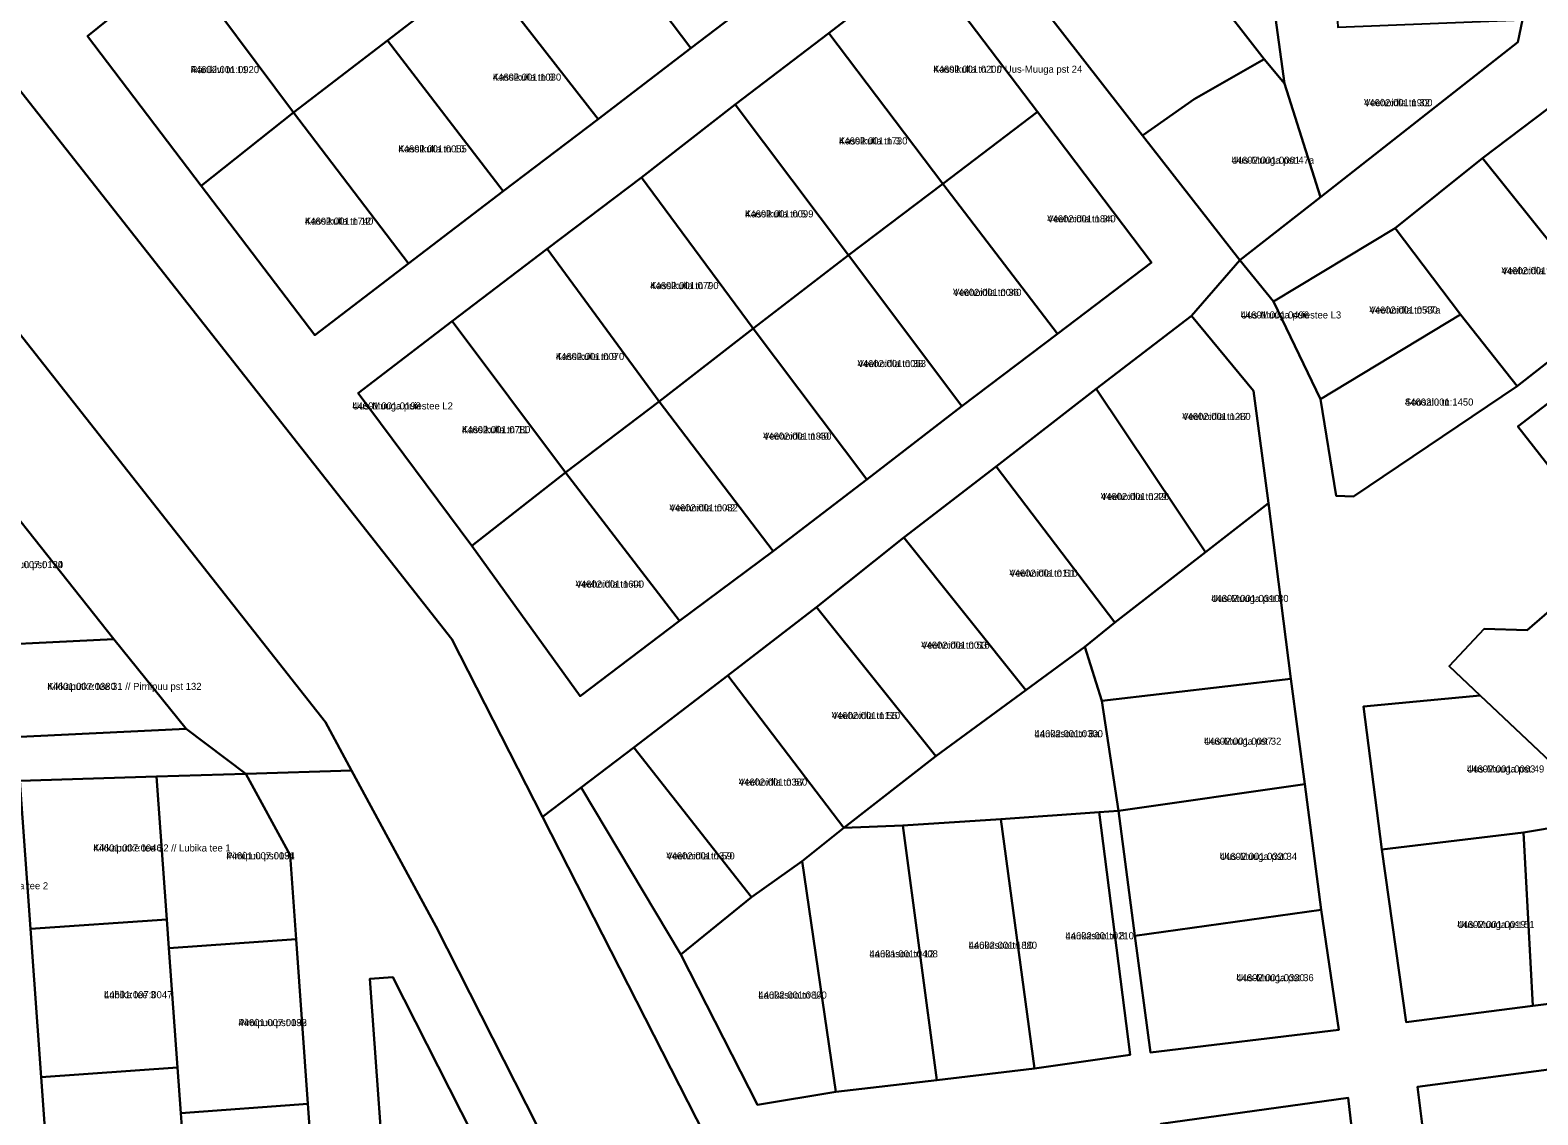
# Model space of a CAD drawing. Extents: x 551843 to 558501, y 6589003 to 6595718.
# Drawn here: x 554378.5 to 554698.1, y 6593216.1 to 6593446 of the extents above; entities that cross this region are included whole.
import ezdxf

# ---------------------------------------------------------------- set-up
doc = ezdxf.new("R2010")
doc.units = 0
for name, color, linetype in [('L_AADRESS', 7, 'Continuous'), ('PIIR', 7, 'Continuous'), ('TUNNUS', 7, 'Continuous')]:
    doc.layers.add(name, color=color, linetype=linetype)

msp = doc.modelspace()

# ---------------------------------------------------------------- linework, layer by layer
at = {"layer": 'PIIR'}
for points in [[(554558.39, 6593472.91), (554533.97, 6593504.96), (554509.47, 6593537.37), (554489.67, 6593522), (554469.89, 6593506.62), (554449.82, 6593491.18), (554430.33, 6593476.01), (554424.48, 6593471.49), (554410.37, 6593460.67), (554390.71, 6593444.69), (554414.79, 6593413.03), (554438.86, 6593381.38), (554458.73, 6593396.56), (554478.79, 6593411.86), (554498.88, 6593427.13), (554518.54, 6593442.19), (554538.24, 6593457.19)], [(554494.38, 6593474.18), (554514.29, 6593489.75), (554538.24, 6593457.19), (554518.54, 6593442.19)], [(554644.4, 6593434.65), (554640.09, 6593439.84), (554616.78, 6593469.9), (554611.24, 6593477.76), (554637.08, 6593488.85), (554641.71, 6593454.64), (554642.5, 6593448.58)], [(554494.38, 6593474.18), (554518.54, 6593442.19), (554498.88, 6593427.13), (554474.07, 6593459.05)], [(554434.36, 6593428.54), (554410.37, 6593460.67), (554424.48, 6593471.49), (554428.06, 6593466.74), (554433.16, 6593460), (554440.31, 6593450.67), (554445.4, 6593449.86), (554457.04, 6593458.74), (554463.12, 6593450.6), (554454.26, 6593443.78)], [(554640.09, 6593439.84), (554625.24, 6593431.4), (554614.3, 6593423.64), (554593.05, 6593450.89), (554596.18, 6593453.39), (554616.78, 6593469.9)], [(554434.36, 6593428.54), (554414.79, 6593413.03), (554390.71, 6593444.69), (554410.37, 6593460.67)], [(554592.06, 6593428.7), (554567.74, 6593460.75), (554547.83, 6593445.37), (554527.95, 6593430.21), (554508.09, 6593414.78), (554488.08, 6593399.67), (554467.99, 6593384.32), (554448.06, 6593369.09), (554472.14, 6593336.71), (554495.13, 6593304.83), (554516.12, 6593320.8), (554536.02, 6593335.58), (554555.87, 6593350.77), (554576, 6593366.27), (554596.28, 6593381.66), (554616.22, 6593396.76)], [(554571.97, 6593413.39), (554547.83, 6593445.37), (554567.74, 6593460.75), (554592.06, 6593428.7)], [(554474.07, 6593459.05), (554498.88, 6593427.13), (554478.79, 6593411.86), (554454.26, 6593443.78), (554463.12, 6593450.6)], [(554642.5, 6593448.58), (554655.54, 6593449.15), (554655.7, 6593446.61), (554694.84, 6593448.21), (554693.84, 6593443.43), (554652, 6593410.62), (554644.4, 6593434.65)], [(554547.83, 6593445.37), (554571.97, 6593413.39), (554551.98, 6593398.31), (554527.95, 6593430.21)], [(554454.26, 6593443.78), (554478.79, 6593411.86), (554458.73, 6593396.56), (554434.36, 6593428.54)], [(554614.3, 6593423.64), (554625.24, 6593431.4), (554640.09, 6593439.84), (554644.4, 6593434.65), (554652, 6593410.62), (554634.9, 6593397.21)], [(554705.79, 6593433.58), (554731.82, 6593401.1), (554723.48, 6593394.34), (554712.94, 6593385.68), (554686.35, 6593418.84)], [(554434.36, 6593428.54), (554458.73, 6593396.56), (554438.86, 6593381.38), (554414.79, 6593413.03)], [(554508.09, 6593414.78), (554527.95, 6593430.21), (554551.98, 6593398.31), (554531.79, 6593382.79)], [(554592.06, 6593428.7), (554616.22, 6593396.76), (554596.28, 6593381.66), (554571.97, 6593413.39)], [(554667.8, 6593404.05), (554686.35, 6593418.84), (554712.94, 6593385.68), (554693.67, 6593370.54), (554681.65, 6593385.7)], [(554531.79, 6593382.79), (554511.87, 6593367.29), (554488.08, 6593399.67), (554508.09, 6593414.78)], [(554571.97, 6593413.39), (554596.28, 6593381.66), (554576, 6593366.27), (554551.98, 6593398.31)], [(554667.8, 6593404.05), (554681.65, 6593385.7), (554651.99, 6593367.81), (554642.02, 6593388.52)], [(554488.08, 6593399.67), (554511.87, 6593367.29), (554491.99, 6593352.28), (554467.99, 6593384.32)], [(554551.98, 6593398.31), (554576, 6593366.27), (554555.87, 6593350.77), (554531.79, 6593382.79)], [(554467.99, 6593384.32), (554491.99, 6593352.28), (554472.14, 6593336.71), (554448.06, 6593369.09)], [(554624.63, 6593385.48), (554637.8, 6593369.53), (554640.97, 6593345.75), (554627.66, 6593335.39), (554604.43, 6593369.96)], [(554681.65, 6593385.7), (554693.67, 6593370.54), (554659.03, 6593347.16), (554655.35, 6593347.33), (554651.99, 6593367.81)], [(554531.79, 6593382.79), (554555.87, 6593350.77), (554536.02, 6593335.58), (554511.87, 6593367.29)], [(554713.27, 6593376.87), (554728.26, 6593376.39), (554730.89, 6593348.69), (554715.53, 6593334.32), (554693.81, 6593362.03)], [(554604.43, 6593369.96), (554627.66, 6593335.39), (554608.44, 6593320.44), (554583.24, 6593353.55)], [(554491.99, 6593352.28), (554511.87, 6593367.29), (554536.02, 6593335.58), (554516.12, 6593320.8)], [(554491.99, 6593352.28), (554516.12, 6593320.8), (554495.13, 6593304.83), (554472.14, 6593336.71)], [(554583.24, 6593353.55), (554608.44, 6593320.44), (554602.09, 6593315.33), (554589.57, 6593306.11), (554563.69, 6593338.49)], [(554358.84, 6593315.1), (554357.18, 6593340.35), (554357.01, 6593347.99), (554370.87, 6593348.86), (554396.28, 6593316.9)], [(554602.09, 6593315.33), (554608.44, 6593320.44), (554627.66, 6593335.39), (554640.97, 6593345.75), (554645.69, 6593308.53), (554605.66, 6593303.87)], [(554563.69, 6593338.49), (554589.57, 6593306.11), (554570.45, 6593292.11), (554545.19, 6593323.7)], [(554686.66, 6593319.08), (554695.78, 6593318.83), (554708.92, 6593330.24), (554724.18, 6593306.39), (554703.25, 6593288.59), (554685.85, 6593304.98), (554679.24, 6593311.2)], [(554545.19, 6593323.7), (554570.45, 6593292.11), (554550.95, 6593276.97), (554526.37, 6593309.22)], [(554358.84, 6593315.1), (554396.28, 6593316.9), (554411.57, 6593297.9), (554360.13, 6593295.44)], [(554563.47, 6593277.43), (554550.95, 6593276.97), (554570.45, 6593292.11), (554589.57, 6593306.11), (554602.09, 6593315.33), (554605.66, 6593303.87), (554609.16, 6593280.58), (554605.1, 6593280.26), (554584.23, 6593278.78)], [(554526.37, 6593309.22), (554550.95, 6593276.97), (554542.17, 6593269.88), (554531.39, 6593262.22), (554506.48, 6593294)], [(554605.66, 6593303.87), (554645.69, 6593308.53), (554648.68, 6593286.23), (554609.16, 6593280.58)], [(554661.09, 6593302.65), (554685.85, 6593304.98), (554703.25, 6593288.59), (554712.28, 6593278.85), (554695.05, 6593275.98), (554664.98, 6593272.36)], [(554506.48, 6593294), (554531.39, 6593262.22), (554516.42, 6593250.12), (554495.31, 6593285.5)], [(554405.33, 6593287.82), (554424.25, 6593288.4), (554433.6, 6593271.12), (554434.88, 6593253.34), (554407.95, 6593251.41), (554407.5, 6593257.53)], [(554405.33, 6593287.82), (554407.5, 6593257.53), (554378.58, 6593255.52), (554376.33, 6593286.93)], [(554609.16, 6593280.58), (554648.68, 6593286.23), (554652.14, 6593259.57), (554612.67, 6593254.06)], [(554563.47, 6593277.43), (554584.23, 6593278.78), (554591.4, 6593225.96), (554570.66, 6593223.48)], [(554584.23, 6593278.78), (554605.1, 6593280.26), (554611.67, 6593228.8), (554591.4, 6593225.96)], [(554712.28, 6593278.85), (554717.2, 6593271.06), (554734.16, 6593243.86), (554697, 6593239.23), (554695.05, 6593275.98)], [(554550.95, 6593276.97), (554563.47, 6593277.43), (554570.66, 6593223.48), (554549.31, 6593220.98), (554542.17, 6593269.88)], [(554695.05, 6593275.98), (554697, 6593239.23), (554670.13, 6593235.73), (554664.98, 6593272.36)], [(554531.39, 6593262.22), (554542.17, 6593269.88), (554549.31, 6593220.98), (554532.71, 6593218.23), (554516.42, 6593250.12)], [(554652.14, 6593259.57), (554655.91, 6593234.16), (554615.95, 6593229.3), (554612.67, 6593254.06)], [(554407.5, 6593257.53), (554407.95, 6593251.41), (554409.76, 6593226.17), (554380.84, 6593224.1), (554378.58, 6593255.52)], [(554434.88, 6593253.34), (554437.39, 6593218.43), (554410.46, 6593216.5), (554409.76, 6593226.17), (554407.95, 6593251.41)], [(554450.52, 6593244.94), (554455.4, 6593245.29), (554481.92, 6593193.06), (554454.39, 6593191.08)], [(554455.4, 6593245.29), (554450.52, 6593244.94), (554454.39, 6593191.08), (554456.32, 6593164.15), (554458.04, 6593140.21), (554460.41, 6593107.3), (554462.99, 6593071.39), (554496.9, 6593073.82), (554494.96, 6593100.76), (554506.93, 6593101.61), (554508.87, 6593074.68), (554540.84, 6593076.98), (554533.65, 6593091.16), (554527.59, 6593103.1), (554506.96, 6593143.72), (554495.17, 6593166.94), (554481.92, 6593193.06)], [(554711.65, 6593227.21), (554715.19, 6593202.16), (554675.67, 6593197.16), (554672.53, 6593222.08)], [(554409.76, 6593226.17), (554410.46, 6593216.5), (554412.02, 6593194.75), (554383.09, 6593192.68), (554380.84, 6593224.1)], [(554412.96, 6593181.59), (554412.02, 6593194.75), (554410.46, 6593216.5), (554437.39, 6593218.43), (554439.89, 6593183.52)], [(554657.88, 6593219.71), (554660.66, 6593195.18), (554621.17, 6593189.78), (554618.16, 6593214.22)]]:
    msp.add_lwpolyline(points, close=True, dxfattribs=at)
for points in [[(554923.69, 6592347.53), (554878.41, 6592438.09), (554841.8, 6592510.41), (554771.18, 6592649.95), (554642.95, 6592903.73), (554573.43, 6593041.09), (554529.22, 6593128.57), (554464.48, 6593256.08), (554446.62, 6593289.09), (554441.09, 6593299.31), (554261.19, 6593527.78)], [(554261.19, 6593527.78), (554441.09, 6593299.31), (554446.62, 6593289.09), (554424.25, 6593288.4), (554411.57, 6593297.9), (554396.28, 6593316.9), (554370.87, 6593348.86)], [(554309.59, 6593518.04), (554467.93, 6593316.95), (554487.14, 6593279.28), (554574.16, 6593108.63)], [(554593.05, 6593450.89), (554614.3, 6593423.64), (554634.9, 6593397.21), (554624.63, 6593385.48), (554604.43, 6593369.96), (554583.24, 6593353.55), (554563.69, 6593338.49), (554545.19, 6593323.7), (554526.37, 6593309.22), (554506.48, 6593294), (554495.31, 6593285.5), (554487.14, 6593279.28), (554467.93, 6593316.95), (554309.59, 6593518.04)], [(554705.79, 6593433.58), (554686.35, 6593418.84), (554667.8, 6593404.05), (554642.02, 6593388.52), (554634.9, 6593397.21), (554652, 6593410.62), (554693.84, 6593443.43), (554694.84, 6593448.21)], [(554574.16, 6593108.63), (554487.14, 6593279.28), (554495.31, 6593285.5), (554516.42, 6593250.12), (554532.71, 6593218.23), (554549.31, 6593220.98), (554570.66, 6593223.48), (554591.4, 6593225.96), (554611.67, 6593228.8), (554605.1, 6593280.26), (554609.16, 6593280.58), (554612.67, 6593254.06), (554615.95, 6593229.3), (554655.91, 6593234.16), (554652.14, 6593259.57), (554648.68, 6593286.23), (554645.69, 6593308.53), (554640.97, 6593345.75), (554637.8, 6593369.53), (554624.63, 6593385.48), (554634.9, 6593397.21), (554642.02, 6593388.52), (554651.99, 6593367.81), (554655.35, 6593347.33), (554659.03, 6593347.16), (554693.67, 6593370.54), (554712.94, 6593385.68)], [(554713.27, 6593376.87), (554693.81, 6593362.03), (554715.53, 6593334.32)], [(554708.92, 6593330.24), (554695.78, 6593318.83), (554686.66, 6593319.08), (554679.24, 6593311.2), (554685.85, 6593304.98), (554661.09, 6593302.65), (554664.98, 6593272.36), (554670.13, 6593235.73), (554697, 6593239.23), (554734.16, 6593243.86)], [(554360.13, 6593295.44), (554411.57, 6593297.9), (554424.25, 6593288.4), (554405.33, 6593287.82), (554376.33, 6593286.93)], [(554439.89, 6593183.52), (554437.39, 6593218.43), (554434.88, 6593253.34), (554433.6, 6593271.12), (554424.25, 6593288.4), (554446.62, 6593289.09), (554464.48, 6593256.08), (554529.22, 6593128.57)], [(554376.33, 6593286.93), (554378.58, 6593255.52), (554380.84, 6593224.1), (554383.09, 6593192.68), (554385.35, 6593161.26), (554387.61, 6593129.84), (554389.86, 6593098.42), (554392.17, 6593066.3), (554393.23, 6593051.33), (554367.77, 6593049.72)], [(554715.19, 6593202.16), (554711.65, 6593227.21), (554672.53, 6593222.08), (554675.67, 6593197.16)], [(554660.66, 6593195.18), (554657.88, 6593219.71), (554618.16, 6593214.22)]]:
    msp.add_lwpolyline(points, dxfattribs=at)

# ---------------------------------------------------------------- texts
at = {"layer": 'L_AADRESS'}
for s, p in [('Ränikivi tn 11', (554412.54, 6593436.88)), ('Kassikulla tn 1 // Uus-Muuga pst 24', (554569.95, 6593436.96)), ('Kassikulla tn 8', (554476.57, 6593435.29)), ('Veehoidla tn 32', (554661.24, 6593429.88)), ('Kassikulla tn 3', (554549.96, 6593421.77)), ('Kassikulla tn 10', (554456.57, 6593420.08)), ('Uus-Muuga pst 47a', (554633.15, 6593417.68)), ('Kassikulla tn 12', (554436.76, 6593404.77)), ('Kassikulla tn 5', (554530.04, 6593406.3)), ('Veehoidla tn 34', (554594.09, 6593405.26)), ('Veehoidla tn 45', (554690.37, 6593394.26)), ('Kassikulla tn 7', (554509.93, 6593391.11)), ('Veehoidla tn 36', (554574.13, 6593389.67)), ('Veehoidla tn 47a', (554662.37, 6593385.93)), ('Uus-Muuga puiestee L3', (554635.09, 6593384.89)), ('Kassikulla tn 9', (554489.93, 6593376.09)), ('Veehoidla tn 38', (554553.89, 6593374.58)), ('Soosalu tn 1', (554669.9, 6593366.43)), ('Uus-Muuga puiestee L2', (554446.82, 6593365.61)), ('Veehoidla tn 47', (554622.7, 6593363.38)), ('Kassikulla tn 11', (554470.03, 6593360.58)), ('Veehoidla tn 40', (554533.87, 6593359.21)), ('Veehoidla tn 42', (554514.01, 6593344.02)), ('Veehoidla tn 49', (554605.45, 6593346.41)), ('Pirnipuu pst 130', (554371.01, 6593331.98)), ('Veehoidla tn 44', (554494.13, 6593327.85)), ('Veehoidla tn 51', (554586.06, 6593330.17)), ('Uus-Muuga pst 30', (554628.84, 6593324.81)), ('Veehoidla tn 53', (554567.38, 6593314.91)), ('Kikkaputke tee 31 // Pirnipuu pst 132', (554382.17, 6593306.17)), ('Veehoidla tn 55', (554548.41, 6593299.99)), ('Laukasoo tn 8a', (554591.39, 6593296.15)), ('Uus-Muuga pst 32', (554627.31, 6593294.55)), ('Uus-Muuga pst 49', (554683.03, 6593288.67)), ('Veehoidla tn 57', (554528.71, 6593285.89)), ('Kikkaputke tee 32 // Lubika tee 1', (554391.91, 6593271.93)), ('Pirnipuu pst 134', (554420.11, 6593270.28)), ('Veehoidla tn 59', (554513.35, 6593270.25)), ('Uus-Muuga pst 34', (554630.65, 6593270.15)), ('Kikkaputke tee 30 // Lubika tee 2', (554353.23, 6593263.91)), ('Uus-Muuga pst 51', (554680.99, 6593255.72)), ('Laukasoo tn 10', (554577.43, 6593251.31)), ('Laukasoo tn 8', (554597.95, 6593253.32)), ('Laukasoo tn 12', (554556.41, 6593249.49)), ('Uus-Muuga pst 36', (554634.17, 6593244.44)), ('Lubika tee 3', (554394.17, 6593240.83)), ('Laukasoo tn 14', (554532.87, 6593240.76)), ('Pirnipuu pst 136', (554422.67, 6593234.92))]:
    msp.add_text(s, height=1.5, dxfattribs=at).set_placement(p)
at = {"layer": 'TUNNUS'}
for s, p in [('44602:001:0920', (554412.54, 6593436.88)), ('44602:001:0200', (554569.95, 6593436.96)), ('44602:001:1030', (554476.57, 6593435.29)), ('44602:001:1900', (554661.24, 6593429.88)), ('44602:001:1730', (554549.96, 6593421.77)), ('44602:001:0055', (554456.57, 6593420.08)), ('44602:001:0061', (554633.15, 6593417.68)), ('44602:001:1740', (554436.76, 6593404.77)), ('44602:001:0099', (554530.04, 6593406.3)), ('44602:001:1840', (554594.09, 6593405.26)), ('44602:001:0520', (554690.37, 6593394.26)), ('44602:001:0790', (554509.93, 6593391.11)), ('44602:001:0040', (554574.13, 6593389.67)), ('44602:001:0530', (554662.37, 6593385.93)), ('44601:001:0496', (554635.09, 6593384.89)), ('44602:001:0070', (554489.93, 6593376.09)), ('44602:001:0053', (554553.89, 6593374.58)), ('44602:001:1450', (554669.9, 6593366.43)), ('44601:001:0198', (554446.82, 6593365.61)), ('44602:001:1280', (554622.7, 6593363.38)), ('44602:001:0780', (554470.03, 6593360.58)), ('44602:001:1850', (554533.87, 6593359.21)), ('44602:001:0082', (554514.01, 6593344.02)), ('44602:001:0220', (554605.45, 6593346.41)), ('44601:007:0124', (554371.01, 6593331.98)), ('44602:001:0110', (554586.06, 6593330.17)), ('44602:001:1600', (554494.13, 6593327.85)), ('44602:001:0310', (554628.84, 6593324.81)), ('44602:001:0016', (554567.38, 6593314.91)), ('44601:007:0380', (554382.17, 6593306.17)), ('44602:001:1110', (554548.41, 6593299.99)), ('44602:001:0300', (554591.39, 6593296.15)), ('44602:001:0097', (554627.31, 6593294.55)), ('44602:001:0063', (554683.03, 6593288.67)), ('44602:001:0380', (554528.71, 6593285.89)), ('44601:007:0046', (554391.91, 6593271.93)), ('44601:007:0091', (554420.11, 6593270.28)), ('44602:001:0370', (554513.35, 6593270.25)), ('44602:001:0320', (554630.65, 6593270.15)), ('44602:001:0019', (554680.99, 6593255.72)), ('44602:001:1880', (554577.43, 6593251.31)), ('44602:001:0210', (554597.95, 6593253.32)), ('44601:001:0408', (554556.41, 6593249.49)), ('44602:001:0330', (554634.17, 6593244.44)), ('44601:007:0047', (554394.17, 6593240.83)), ('44602:001:0800', (554532.87, 6593240.76)), ('44601:007:0092', (554422.67, 6593234.92))]:
    msp.add_text(s, height=1.5, dxfattribs=at).set_placement(p)

doc.saveas('drawing.dxf')
